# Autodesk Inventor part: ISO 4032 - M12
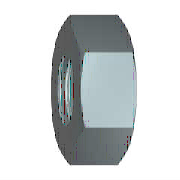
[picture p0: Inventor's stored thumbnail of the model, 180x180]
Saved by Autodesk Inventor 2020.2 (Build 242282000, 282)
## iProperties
Manager: www.cadconsulting.pl
Company: Fabian Stasiak CAD Consulting
IsCustomPart: 0
Created: 2010-02
Part Number: ISO 4032 - M12
Material: Stal nierdzewna, 440C
Description: Nakrętki sześciokątne, styl 1 - Klasa dokładności A i B
Document SubType Name: Modeling
Standard: ISO 4032
Designer: F.Stasiak
Standard Revision: Third edition 1999-08-15
Standards Organization: ISO
Language: pl-PL
Size Designation: M12
Categories: <MemberInstance><Categories><Category DisplayName="Mocowania" InternalName="e4da775c-781d-43d5-af7c-5136215cf5a6" Mnemonic="FSTN"><Category DisplayName="Nakrętk
Density: 7.75 g/cm^3
Appearance: Metal-Stal
Author: F.Stasiak
Subject: Zbiór ćwiczeń. Autodesk Inventor 2020. Kurs podstawowy
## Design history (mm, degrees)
sketch "Sketch1"
  geometry: L1 (-10.392, 0)-(-5.196, 9); L2 (-5.196, 9)-(5.196, 9); L3 (5.196, 9)-(10.392, 0); L4 (10.392, 0)-(5.196, -9); L5 (5.196, -9)-(-5.196, -9); L6 (-5.196, -9)-(-10.392, 0); 2 further points
  constraints: 12 end point, 1 coincident, 1 horizontal, 11 other
  dimensions: "d0" = 20.78461 distance of L3.end L1.start (= 1.1547 x SW)
extrude "Body" new body sketch "Sketch1" distance "d1" = 10.8 (= KOH); taper "d2" = 0 deg
sketch "Sketch2"
  geometry: L1 (0, 5.196)-(0, 10.392) reference; L2 (0, 10.392)-(10.8, 10.392) reference; L3 (10.8, 5.196)-(10.8, 10.392) reference; L4 (-2.16, 0)-(12.96, 0) reference; L5 (1.208, 10.392)-(0, 8.3); L6 (9.592, 10.392)-(10.8, 8.3)
  constraints: 4 end point, 4 point on line
  dimensions: "d3" = 30 deg angle of L1 L5 (= ANG1); "d4" = 30 deg angle of L3 L6 (= ANG2); "d5" = 16.6 diameter of L5.end L4 (= SW0); "d6" = 16.6 diameter of L6.end L4 (= SW01)
revolve "Chamfer1" sketch "Sketch2" stored, may be unused: angle "d7" = 90 deg
sketch "Sketch3"
  geometry: 4 further points
  constraints: 1 coincident, 1 other
hole "Thread" sketch "Sketch3" at (0, 0) diameter "d25" = 10.106; stored, may be unused: countersink angle "d29" = 82 deg, drill point angle "d31" = 118 deg; dims "d26" = 6, "d27" = 4, "d28" = 2, "d30" = 8
chamfer "Chamfer2" distance "d8" = 0.94722 (= -0.5 x GD1 + 0.5 x NND); stored, may be unused: angle "d9" = 30 deg, second distance "d40" = 0.94722 (= -0.5 x GD1 + 0.5 x NND)
chamfer "Chamfer3" distance "d10" = 0.94722 (= -0.5 x GD1 + 0.5 x NND); stored, may be unused: angle "d11" = 30 deg, second distance "d41" = 0.94722 (= -0.5 x GD1 + 0.5 x NND)
workaxis "Work Axis1"
workplane "Work Plane1"
body "Solid1"
other parameters: "ANG1" = 30 deg [user parameter; used in 1 equation term], "ANG2" = 30 deg [user parameter; used in 1 equation term], "NND" = 12 [user parameter; used in 4 equation terms], "KOH" = 10.8 [user parameter; used in 1 equation term], "SW" = 18 [user parameter; used in 2 equation terms], "SW0" = 16.6 [user parameter; used in 2 equation terms], "SW01" = 16.6 (= SW0) [user parameter; used in 1 equation term], "GD1" = 10.10557 (computed from THREADDIA, PTC, TOA) [user parameter; used in 4 equation terms], "d13" = 0, "d14" = 0, "d39" = 0, "d42" = 0, "GUL" = 0.94722 (= 0.541266 x PTC) [user parameter], "TPU" = 5.71429 (computed from PTC) [user parameter], "THREADDIA" = 12 [user parameter; used in 1 equation term], "TOA" = 30 deg [user parameter; used in 1 equation term], "PTC" = 1.75 [user parameter; used in 4 equation terms], "E0" = 20.79 (= 1.155 x SW) [user parameter], "GAL" = 0.94722 (= 0.541266 x PTC) [user parameter]
